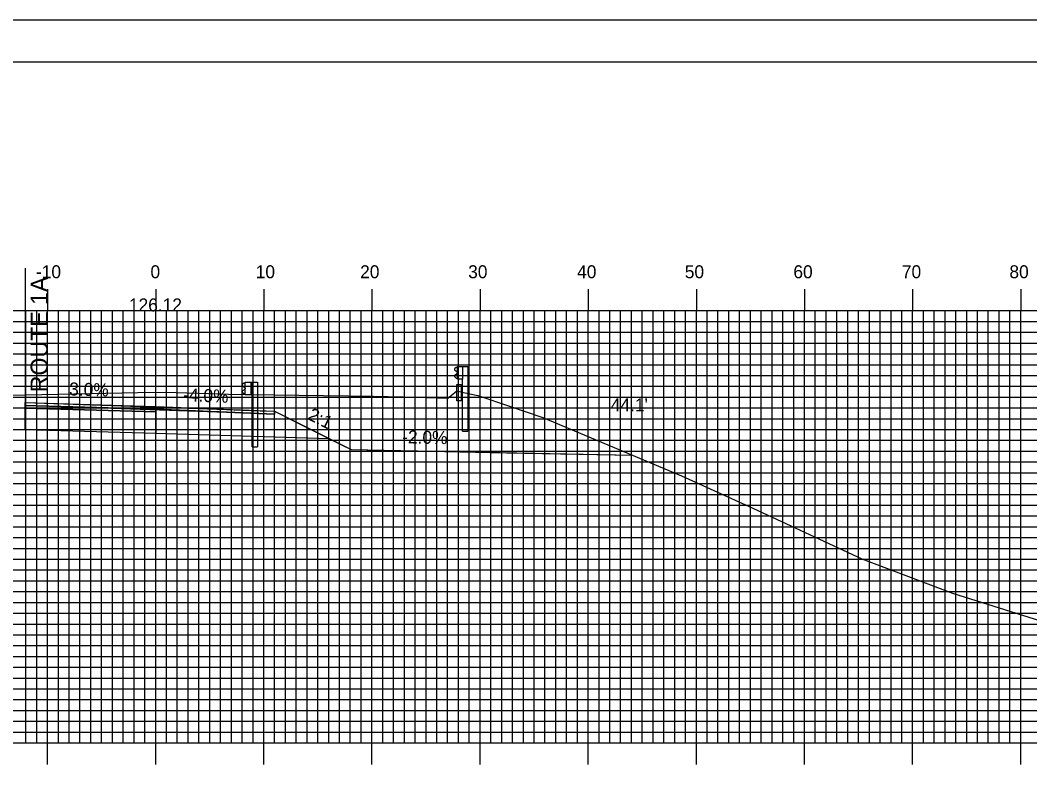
# Model space of a CAD drawing. Extents: x 858052 to 858395, y 364366 to 364586.
# Drawn here: x 858204.8 to 858298.2, y 364516.3 to 364585.7 of the extents above; entities that cross this region are included whole.
import ezdxf

# ---------------------------------------------------------------- set-up
doc = ezdxf.new("R2010")
doc.units = 0
for name, color, linetype in [('ANNOTATION', 7, 'Continuous'), ('BORDER', 7, 'Continuous'), ('D_Guardrail_Beam_Lt', 7, 'Continuous'), ('D_Roadway_Centerline', 7, 'Continuous'), ('D_Roadway_Centerline_Text', 7, 'Continuous'), ('D_Roadway_Edge_Shoulder', 7, 'Continuous'), ('D_Roadway_Edge_TW', 7, 'Continuous'), ('D_Roadway_Pavement', 7, 'Continuous'), ('D_Roadway_SlopeLines', 7, 'Continuous'), ('D_Roadway_SubGrade', 7, 'Continuous'), ('D_Text_Standard', 7, 'Continuous'), ('H_V ANNOTATION', 7, 'Continuous'), ('M_Roadway_Centerline', 7, 'Continuous'), ('MAJOR', 7, 'Continuous'), ('MINOR', 7, 'Continuous'), ('PLOT BOUNDARY', 7, 'Continuous'), ('S_Curb_Type_1', 7, 'Continuous'), ('S_Guardrail_Beam', 7, 'Continuous'), ('S_Roadway_Centerline', 7, 'Continuous')]:
    doc.layers.add(name, color=color, linetype=linetype)

msp = doc.modelspace()

# ---------------------------------------------------------------- linework, layer by layer
at = {"layer": 'BORDER'}
msp.add_lwpolyline([(858067.762, 364371.787), (858387.762, 364371.787), (858387.762, 364581.787), (858067.762, 364581.787)], close=True, dxfattribs=at)
at = {"layer": 'D_Guardrail_Beam_Lt'}
for p, q in [((858225.632, 364552.173), (858226.32, 364552.173)), ((858225.632, 364551.006), (858225.632, 364552.173)), ((858226.153, 364552.173), (858226.153, 364551.006)), ((858226.257, 364552.173), (858226.257, 364551.006)), ((858226.32, 364552.173), (858226.791, 364552.173)), ((858226.32, 364552.173), (858226.32, 364551.006)), ((858226.791, 364552.173), (858226.791, 364546.173)), ((858225.542, 364552.069), (858225.399, 364551.969)), ((858225.399, 364551.825), (858225.594, 364551.689)), ((858225.594, 364551.49), (858225.399, 364551.354)), ((858225.632, 364552.09), (858225.558, 364552.075)), ((858225.628, 364551.625), (858225.628, 364551.555)), ((858225.399, 364551.211), (858225.542, 364551.111)), ((858225.558, 364551.104), (858225.632, 364551.09)), ((858226.32, 364551.006), (858225.632, 364551.006)), ((858226.299, 364546.173), (858226.299, 364551.006)), ((858226.299, 364546.173), (858226.791, 364546.173))]:
    msp.add_line(p, q, dxfattribs=at)
for centre, major_axis, start_param, end_param in [((858225.449, 364551.897), (-0.0877, 0), 5.323254, 7.243116), ((858225.449, 364551.283), (-0.0877, 0), 5.323254, 7.243116), ((858225.566, 364552.035), (-0.0417, 0), 4.907132, 5.323254), ((858225.549, 364551.625), (0.0789, 0), 0, 0.959931), ((858225.549, 364551.555), (0.0789, 0), 5.323254, 6.283185), ((858225.566, 364551.145), (-0.0417, 0), 0.959931, 1.376053)]:
    msp.add_ellipse(centre, major_axis=major_axis, ratio=0.995501, start_param=start_param, end_param=end_param, dxfattribs=at)
at = {"layer": 'D_Roadway_Centerline'}
msp.add_lwpolyline([(858205.304, 364550.272), (858211.84, 364550.075), (858217.362, 364549.91), (858221.772, 364549.733), (858225.362, 364549.59), (858227.014, 364549.524), (858228.362, 364549.47), (858231.164, 364548.069), (858233.447, 364546.927), (858234.548, 364546.376), (858235.447, 364545.927), (858249.802, 364545.64), (858261.476, 364545.407)], dxfattribs=at)
at = {"layer": 'D_Roadway_Edge_Shoulder'}
for points in [[(858205.304, 364550.272), (858228.362, 364549.47), (858228.362, 364549.22), (858205.304, 364550.022)], [(858217.362, 364549.91), (858228.362, 364549.47), (858228.362, 364549.22), (858217.362, 364549.66)], [(858217.362, 364549.91), (858225.362, 364549.59), (858225.362, 364549.59), (858228.362, 364549.47), (858228.362, 364549.22), (858217.362, 364549.66)]]:
    msp.add_lwpolyline(points, close=True, dxfattribs=at)
at = {"layer": 'D_Roadway_Edge_TW'}
for points in [[(858205.304, 364550.272), (858217.362, 364549.91), (858217.362, 364549.66), (858205.304, 364550.022)], [(858205.304, 364550.272), (858217.362, 364549.91), (858217.362, 364549.66), (858205.304, 364550.022)], [(858205.304, 364550.272), (858217.362, 364549.91), (858217.362, 364549.66), (858205.304, 364550.022)], [(858205.304, 364550.272), (858205.304, 364550.272), (858205.304, 364550.022), (858205.304, 364550.022)]]:
    msp.add_lwpolyline(points, close=True, dxfattribs=at)
at = {"layer": 'D_Roadway_Pavement'}
for points in [[(858205.304, 364550.022), (858217.362, 364549.66), (858217.362, 364549.41), (858205.304, 364549.772)], [(858205.304, 364550.022), (858205.304, 364550.022), (858205.304, 364549.772), (858205.304, 364549.772)], [(858205.304, 364550.022), (858217.362, 364549.66), (858217.362, 364549.41), (858205.304, 364549.772)], [(858205.304, 364550.022), (858217.362, 364549.66), (858217.362, 364549.41), (858205.304, 364549.772)]]:
    msp.add_lwpolyline(points, close=True, dxfattribs=at)
msp.add_lwpolyline([(858217.362, 364549.66), (858217.362, 364549.41)], dxfattribs=at)
msp.add_lwpolyline([(858217.362, 364549.66), (858217.362, 364549.41)], dxfattribs=at)
msp.add_lwpolyline([(858217.362, 364549.66), (858217.362, 364549.41)], dxfattribs=at)
msp.add_lwpolyline([(858217.362, 364549.66), (858217.362, 364549.41)], dxfattribs=at)
at = {"layer": 'D_Roadway_SlopeLines'}
for points in [[(858228.362, 364549.47), (858235.447, 364545.927)], [(858235.447, 364545.927), (858261.476, 364545.407)]]:
    msp.add_lwpolyline(points, dxfattribs=at)
at = {"layer": 'D_Roadway_SubGrade'}
msp.add_line((858205.304, 364562.729), (858205.304, 364547.772), dxfattribs=at)
for points in [[(858205.304, 364549.772), (858217.362, 364549.41), (858217.362, 364547.41), (858205.304, 364547.772)], [(858205.304, 364549.772), (858205.304, 364549.772), (858205.304, 364547.772), (858205.304, 364547.772)], [(858205.304, 364549.772), (858217.362, 364549.41), (858217.362, 364547.41), (858205.304, 364547.772)], [(858205.304, 364549.772), (858217.362, 364549.41), (858217.362, 364547.41), (858205.304, 364547.772)], [(858217.362, 364549.41), (858217.362, 364549.66), (858228.362, 364549.22), (858228.362, 364549.47), (858233.447, 364546.927), (858217.362, 364547.41)]]:
    msp.add_lwpolyline(points, close=True, dxfattribs=at)
at = {"layer": 'MAJOR'}
for p, q in [((858207.362, 364560.791), (858207.362, 364558.787)), ((858217.362, 364560.791), (858217.362, 364558.787)), ((858227.362, 364560.791), (858227.362, 364558.787)), ((858237.362, 364560.791), (858237.362, 364558.787)), ((858247.362, 364560.791), (858247.362, 364558.787)), ((858257.362, 364560.791), (858257.362, 364558.787)), ((858267.362, 364560.791), (858267.362, 364558.787)), ((858277.362, 364560.791), (858277.362, 364558.787)), ((858287.362, 364560.791), (858287.362, 364558.787)), ((858297.362, 364560.791), (858297.362, 364558.787)), ((858077.362, 364558.787), (858357.362, 364558.787)), ((858077.362, 364558.787), (858357.362, 364558.787)), ((858207.362, 364518.787), (858207.362, 364558.787)), ((858217.362, 364518.787), (858217.362, 364558.787)), ((858227.362, 364518.787), (858227.362, 364558.787)), ((858237.362, 364518.787), (858237.362, 364558.787)), ((858247.362, 364518.787), (858247.362, 364558.787)), ((858257.362, 364518.787), (858257.362, 364558.787)), ((858267.362, 364518.787), (858267.362, 364558.787)), ((858277.362, 364518.787), (858277.362, 364558.787)), ((858287.362, 364518.787), (858287.362, 364558.787)), ((858297.362, 364518.787), (858297.362, 364558.787)), ((858077.362, 364553.787), (858357.362, 364553.787)), ((858077.362, 364548.787), (858357.362, 364548.787)), ((858077.362, 364543.787), (858357.362, 364543.787)), ((858077.362, 364538.787), (858357.362, 364538.787)), ((858077.362, 364533.787), (858357.362, 364533.787)), ((858077.362, 364528.787), (858357.362, 364528.787)), ((858077.362, 364523.787), (858357.362, 364523.787)), ((858077.362, 364518.787), (858357.362, 364518.787)), ((858077.362, 364518.787), (858357.362, 364518.787)), ((858207.362, 364516.783), (858207.362, 364518.787)), ((858217.362, 364516.783), (858217.362, 364518.787)), ((858227.362, 364516.783), (858227.362, 364518.787)), ((858237.362, 364516.783), (858237.362, 364518.787)), ((858247.362, 364516.783), (858247.362, 364518.787)), ((858257.362, 364516.783), (858257.362, 364518.787)), ((858267.362, 364516.783), (858267.362, 364518.787)), ((858277.362, 364516.783), (858277.362, 364518.787)), ((858287.362, 364516.783), (858287.362, 364518.787)), ((858297.362, 364516.783), (858297.362, 364518.787))]:
    msp.add_line(p, q, dxfattribs=at)
at = {"layer": 'MINOR'}
for p, q in [((858205.362, 364518.787), (858205.362, 364558.787)), ((858206.362, 364518.787), (858206.362, 364558.787)), ((858208.362, 364518.787), (858208.362, 364558.787)), ((858209.362, 364518.787), (858209.362, 364558.787)), ((858210.362, 364518.787), (858210.362, 364558.787)), ((858211.362, 364518.787), (858211.362, 364558.787)), ((858212.362, 364518.787), (858212.362, 364558.787)), ((858213.362, 364518.787), (858213.362, 364558.787)), ((858214.362, 364518.787), (858214.362, 364558.787)), ((858215.362, 364518.787), (858215.362, 364558.787)), ((858216.362, 364518.787), (858216.362, 364558.787)), ((858218.362, 364518.787), (858218.362, 364558.787)), ((858219.362, 364518.787), (858219.362, 364558.787)), ((858220.362, 364518.787), (858220.362, 364558.787)), ((858221.362, 364518.787), (858221.362, 364558.787)), ((858222.362, 364518.787), (858222.362, 364558.787)), ((858223.362, 364518.787), (858223.362, 364558.787)), ((858224.362, 364518.787), (858224.362, 364558.787)), ((858225.362, 364518.787), (858225.362, 364558.787)), ((858226.362, 364518.787), (858226.362, 364558.787)), ((858228.362, 364518.787), (858228.362, 364558.787)), ((858229.362, 364518.787), (858229.362, 364558.787)), ((858230.362, 364518.787), (858230.362, 364558.787)), ((858231.362, 364518.787), (858231.362, 364558.787)), ((858232.362, 364518.787), (858232.362, 364558.787)), ((858233.362, 364518.787), (858233.362, 364558.787)), ((858234.362, 364518.787), (858234.362, 364558.787)), ((858235.362, 364518.787), (858235.362, 364558.787)), ((858236.362, 364518.787), (858236.362, 364558.787)), ((858238.362, 364518.787), (858238.362, 364558.787)), ((858239.362, 364518.787), (858239.362, 364558.787)), ((858240.362, 364518.787), (858240.362, 364558.787)), ((858241.362, 364518.787), (858241.362, 364558.787)), ((858242.362, 364518.787), (858242.362, 364558.787)), ((858243.362, 364518.787), (858243.362, 364558.787)), ((858244.362, 364518.787), (858244.362, 364558.787)), ((858245.362, 364518.787), (858245.362, 364558.787)), ((858246.362, 364518.787), (858246.362, 364558.787)), ((858248.362, 364518.787), (858248.362, 364558.787)), ((858249.362, 364518.787), (858249.362, 364558.787)), ((858250.362, 364518.787), (858250.362, 364558.787)), ((858251.362, 364518.787), (858251.362, 364558.787)), ((858252.362, 364518.787), (858252.362, 364558.787)), ((858253.362, 364518.787), (858253.362, 364558.787)), ((858254.362, 364518.787), (858254.362, 364558.787)), ((858255.362, 364518.787), (858255.362, 364558.787)), ((858256.362, 364518.787), (858256.362, 364558.787)), ((858258.362, 364518.787), (858258.362, 364558.787)), ((858259.362, 364518.787), (858259.362, 364558.787)), ((858260.362, 364518.787), (858260.362, 364558.787)), ((858261.362, 364518.787), (858261.362, 364558.787)), ((858262.362, 364518.787), (858262.362, 364558.787)), ((858263.362, 364518.787), (858263.362, 364558.787)), ((858264.362, 364518.787), (858264.362, 364558.787)), ((858265.362, 364518.787), (858265.362, 364558.787)), ((858266.362, 364518.787), (858266.362, 364558.787)), ((858268.362, 364518.787), (858268.362, 364558.787)), ((858269.362, 364518.787), (858269.362, 364558.787)), ((858270.362, 364518.787), (858270.362, 364558.787)), ((858271.362, 364518.787), (858271.362, 364558.787)), ((858272.362, 364518.787), (858272.362, 364558.787)), ((858273.362, 364518.787), (858273.362, 364558.787)), ((858274.362, 364518.787), (858274.362, 364558.787)), ((858275.362, 364518.787), (858275.362, 364558.787)), ((858276.362, 364518.787), (858276.362, 364558.787)), ((858278.362, 364518.787), (858278.362, 364558.787)), ((858279.362, 364518.787), (858279.362, 364558.787)), ((858280.362, 364518.787), (858280.362, 364558.787)), ((858281.362, 364518.787), (858281.362, 364558.787)), ((858282.362, 364518.787), (858282.362, 364558.787)), ((858283.362, 364518.787), (858283.362, 364558.787)), ((858284.362, 364518.787), (858284.362, 364558.787)), ((858285.362, 364518.787), (858285.362, 364558.787)), ((858286.362, 364518.787), (858286.362, 364558.787)), ((858288.362, 364518.787), (858288.362, 364558.787)), ((858289.362, 364518.787), (858289.362, 364558.787)), ((858290.362, 364518.787), (858290.362, 364558.787)), ((858291.362, 364518.787), (858291.362, 364558.787)), ((858292.362, 364518.787), (858292.362, 364558.787)), ((858293.362, 364518.787), (858293.362, 364558.787)), ((858294.362, 364518.787), (858294.362, 364558.787)), ((858295.362, 364518.787), (858295.362, 364558.787)), ((858296.362, 364518.787), (858296.362, 364558.787)), ((858077.362, 364557.787), (858357.362, 364557.787)), ((858077.362, 364556.787), (858357.362, 364556.787)), ((858077.362, 364555.787), (858357.362, 364555.787)), ((858077.362, 364554.787), (858357.362, 364554.787)), ((858077.362, 364552.787), (858357.362, 364552.787)), ((858077.362, 364551.787), (858357.362, 364551.787)), ((858077.362, 364550.787), (858357.362, 364550.787)), ((858077.362, 364549.787), (858357.362, 364549.787)), ((858077.362, 364547.787), (858357.362, 364547.787)), ((858077.362, 364546.787), (858357.362, 364546.787)), ((858077.362, 364545.787), (858357.362, 364545.787)), ((858077.362, 364544.787), (858357.362, 364544.787)), ((858077.362, 364542.787), (858357.362, 364542.787)), ((858077.362, 364541.787), (858357.362, 364541.787)), ((858077.362, 364540.787), (858357.362, 364540.787)), ((858077.362, 364539.787), (858357.362, 364539.787)), ((858077.362, 364537.787), (858357.362, 364537.787)), ((858077.362, 364536.787), (858357.362, 364536.787)), ((858077.362, 364535.787), (858357.362, 364535.787)), ((858077.362, 364534.787), (858357.362, 364534.787)), ((858077.362, 364532.787), (858357.362, 364532.787)), ((858077.362, 364531.787), (858357.362, 364531.787)), ((858077.362, 364530.787), (858357.362, 364530.787)), ((858077.362, 364529.787), (858357.362, 364529.787)), ((858077.362, 364527.787), (858357.362, 364527.787)), ((858077.362, 364526.787), (858357.362, 364526.787)), ((858077.362, 364525.787), (858357.362, 364525.787)), ((858077.362, 364524.787), (858357.362, 364524.787)), ((858077.362, 364522.787), (858357.362, 364522.787)), ((858077.362, 364521.787), (858357.362, 364521.787)), ((858077.362, 364520.787), (858357.362, 364520.787)), ((858077.362, 364519.787), (858357.362, 364519.787))]:
    msp.add_line(p, q, dxfattribs=at)
at = {"layer": 'PLOT BOUNDARY'}
msp.add_lwpolyline([(858051.575, 364365.669), (858391.575, 364365.669), (858391.575, 364585.669), (858051.575, 364585.669)], close=True, dxfattribs=at)
at = {"layer": 'S_Curb_Type_1'}
msp.add_lwpolyline([(858245.197, 364551.955), (858245.613, 364551.955), (858245.613, 364550.455), (858245.197, 364550.455)], close=True, dxfattribs=at)
msp.add_lwpolyline([(858245.197, 364551.955), (858245.613, 364551.955), (858245.613, 364550.455), (858245.197, 364550.455)], close=True, dxfattribs=at)
at = {"layer": 'S_Guardrail_Beam'}
for p, q in [((858245.162, 364553.53), (858245.018, 364553.43)), ((858245.162, 364553.53), (858245.018, 364553.43)), ((858245.018, 364553.287), (858245.214, 364553.151)), ((858245.018, 364553.287), (858245.214, 364553.151)), ((858245.261, 364553.551), (858245.179, 364553.537)), ((858245.261, 364553.551), (858245.179, 364553.537)), ((858245.247, 364553.086), (858245.247, 364552.995)), ((858245.247, 364553.086), (858245.247, 364552.995)), ((858245.261, 364553.624), (858245.75, 364553.624)), ((858245.261, 364552.458), (858245.261, 364553.624)), ((858245.261, 364553.624), (858245.75, 364553.624)), ((858245.261, 364552.458), (858245.261, 364553.624)), ((858245.75, 364553.624), (858246.242, 364553.624)), ((858245.75, 364553.624), (858245.75, 364552.458)), ((858245.75, 364553.624), (858246.242, 364553.624)), ((858245.75, 364553.624), (858245.75, 364552.458)), ((858246.242, 364553.624), (858246.242, 364547.624)), ((858246.242, 364553.624), (858246.242, 364547.624)), ((858245.214, 364552.931), (858245.018, 364552.795)), ((858245.214, 364552.931), (858245.018, 364552.795)), ((858245.018, 364552.652), (858245.162, 364552.552)), ((858245.018, 364552.652), (858245.162, 364552.552)), ((858245.179, 364552.545), (858245.261, 364552.531)), ((858245.179, 364552.545), (858245.261, 364552.531)), ((858245.75, 364552.458), (858245.261, 364552.458)), ((858245.75, 364552.458), (858245.261, 364552.458)), ((858245.75, 364547.624), (858245.75, 364552.458)), ((858245.75, 364547.624), (858245.75, 364552.458)), ((858245.75, 364547.624), (858246.242, 364547.624)), ((858245.75, 364547.624), (858246.242, 364547.624))]:
    msp.add_line(p, q, dxfattribs=at)
for centre, major_axis, start_param, end_param in [((858245.069, 364553.359), (-0.0877, 0), 5.323254, 7.243116), ((858245.069, 364553.359), (-0.0877, 0), 5.323254, 7.243116), ((858245.186, 364553.496), (-0.0417, 0), 4.886922, 5.323254), ((858245.186, 364553.496), (-0.0417, 0), 4.886922, 5.323254), ((858245.168, 364553.086), (0.0789, 0), 0, 0.959931), ((858245.168, 364553.086), (0.0789, 0), 0, 0.959931), ((858245.069, 364552.723), (-0.0877, 0), 5.323254, 7.243116), ((858245.069, 364552.723), (-0.0877, 0), 5.323254, 7.243116), ((858245.186, 364552.586), (-0.0417, 0), 0.959931, 1.396263), ((858245.186, 364552.586), (-0.0417, 0), 0.959931, 1.396263), ((858245.168, 364552.995), (0.0789, 0), 5.323254, 6.283185), ((858245.168, 364552.995), (0.0789, 0), 5.323254, 6.283185)]:
    msp.add_ellipse(centre, major_axis=major_axis, ratio=0.995501, start_param=start_param, end_param=end_param, dxfattribs=at)
at = {"layer": 'S_Roadway_Centerline'}
msp.add_lwpolyline([(858200.847, 364550.903), (858211.285, 364551.109), (858215.702, 364551.198), (858218.225, 364551.237), (858222.262, 364551.116), (858224.105, 364551.07), (858225.97, 364551.032), (858237.493, 364550.866), (858240.256, 364550.812), (858244.389, 364550.681), (858244.687, 364550.94), (858245.197, 364551.372), (858245.834, 364551.217), (858247.164, 364550.929), (858250.081, 364549.959), (858253.158, 364548.912), (858266.003, 364543.499), (858272.58, 364540.508), (858282.657, 364535.807), (858291.044, 364532.64), (858299.684, 364529.941)], dxfattribs=at)

# ---------------------------------------------------------------- texts
at = {"layer": 'ANNOTATION'}
for s, height, rotation, p in [('ROUTE 1A', 1.6, 90, (858207.396, 364551.233)), ('3.0%', 1.2, 358.28156, (858209.35, 364550.951)), ('-4.0%', 1.2, 357.70939, (858219.884, 364550.42)), ('2:1', 1.2, 333.43495, (858231.331, 364548.776)), ('-2.0%', 1.2, 358.85424, (858240.146, 364546.514))]:
    msp.add_text(s, height=height, rotation=rotation, dxfattribs=at).set_placement(p)
at = {"layer": 'D_Roadway_Centerline_Text'}
msp.add_text('126.12', height=1.2, dxfattribs=at).set_placement((858214.884, 364558.718))
at = {"layer": 'D_Text_Standard'}
msp.add_text("44.1'", height=1.2, dxfattribs=at).set_placement((858259.446, 364549.462))
at = {"layer": 'H_V ANNOTATION'}
for s, p in [('-10', (858206.291, 364561.787)), ('0', (858216.88, 364561.787)), ('10', (858226.612, 364561.787)), ('20', (858236.27, 364561.787)), ('30', (858246.259, 364561.787)), ('40', (858256.334, 364561.787)), ('50', (858266.291, 364561.787)), ('60', (858276.334, 364561.787)), ('70', (858286.366, 364561.787)), ('80', (858296.312, 364561.787))]:
    msp.add_text(s, height=1.2, dxfattribs=at).set_placement(p)
at = {"layer": 'M_Roadway_Centerline'}
for s, p in [('C', (858218.22, 364551.237)), ('L', (858218.225, 364551.23))]:
    msp.add_text(s, height=0.0146, dxfattribs=at).set_placement(p)

doc.saveas('drawing.dxf')
